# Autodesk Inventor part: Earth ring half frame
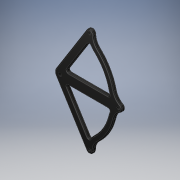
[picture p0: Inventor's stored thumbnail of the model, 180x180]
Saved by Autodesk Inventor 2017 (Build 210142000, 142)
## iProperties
Created: 2016-06
Part Number: Earth ring half frame
Material: Generic
Document SubType Name: Modeling
Designer: Stan
Density: 1 g/cm^3
Appearance: Glossy - Black
Author: Stan
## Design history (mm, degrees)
sketch "Sketch1"
  geometry: L1 (-8.091, -5.025)-(47.159, -93.985); L2 (47.665, 93.707)-(-8.064, 5.07); L3 (15.486, 9.525)-(85.613, 9.525); L4 (15.363, -9.525)-(85.613, -9.525); L5 (12.666, -14.375)-(48.934, -72.77); L6 (12.798, 14.39)-(49.328, 72.492); C1 r 2.54 at (104.775, 0); C2 r 2.54 at (52.554, -90.635); C3 r 2.54 at (53.041, 90.327); C4 r 3.175 at (0, 0); A1 r 98.425 centre (0, 0) between (66.878, -72.213) and (95.978, -21.812); A2 r 98.425 centre (0, 0) between (95.978, 21.812) and (66.878, 72.213); A3 r 6.35 centre (104.775, 0) between (107.969, -5.488) and (107.969, 5.488); A4 r 25.4 centre (120.746, 27.441) between (95.978, 21.812) and (107.969, 5.488); A5 r 25.4 centre (120.746, -27.441) between (107.969, -5.488) and (95.978, -21.812); A6 r 6.35 centre (52.554, -90.635) between (47.159, -93.985) and (58.904, -90.657); A7 r 25.4 centre (84.304, -90.694) between (66.878, -72.213) and (58.904, -90.657); A8 r 6.35 centre (53.041, 90.327) between (59.39, 90.349) and (47.665, 93.707); A9 r 25.4 centre (84.79, 90.222) between (59.39, 90.349) and (66.878, 72.213); A10 r 34.921 centre (84.79, 90.222) between (54.748, 72.421) and (60.406, 65.225); A11 r 34.925 centre (84.304, -90.694) between (60.378, -65.251) and (54.353, -72.728); A12 r 88.9 centre (0, 0) between (60.378, -65.251) and (86.69, -19.701); A13 r 34.925 centre (120.746, -27.441) between (88.541, -13.928) and (86.69, -19.701); A14 r 34.925 centre (120.746, 27.441) between (86.69, 19.701) and (88.541, 13.928); A15 r 88.9 centre (0, 0) between (86.69, 19.701) and (60.295, 65.328); A16 r 9.525 centre (0, 0) between (-8.064, 5.07) and (-8.091, -5.025); A17 r 3.175 centre (85.613, 12.7) between (85.613, 9.525) and (88.541, 13.928); A18 r 3.175 centre (85.613, -12.7) between (88.541, -13.928) and (85.613, -9.525); A19 r 3.175 centre (52.016, 70.803) between (54.748, 72.421) and (49.328, 72.492); A20 r 3.175 centre (15.486, 12.7) between (12.798, 14.39) and (15.486, 9.525); A21 r 3.175 centre (15.363, -12.7) between (15.363, -9.525) and (12.666, -14.375); A22 r 3.175 centre (51.631, -71.095) between (48.934, -72.77) and (54.353, -72.728); 9 further points
  constraints: 47 point on circle, 26 centre point, 14 tangent, 12 end point, 4 equal radius, 2 parallel, 2 point on line, 1 coincident, 4 other
  dimensions: "d22" = 6.35 diameter of C4; "d24" = 5.08 diameter of C3; "d27" = 3.175 radius of A17 (derived); "d31" = 12.7 distance between parallel lines of L2 L6; "d32" = 12.7 distance between parallel lines of L1 L5; "d33" = 3.175 radius of A19 (derived)
extrude "Extrusion3" new body sketch "Sketch1" distance "d28" = 6.35; taper "d29" = 0 deg
fillet "Fillet2" dims "d30" = 1.5875
fillet "Fillet3" dims "d34" = 1.5875
fillet "Fillet4" dims "d35" = 1.5875
body "Solid2"
